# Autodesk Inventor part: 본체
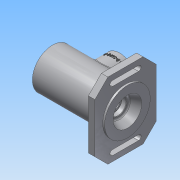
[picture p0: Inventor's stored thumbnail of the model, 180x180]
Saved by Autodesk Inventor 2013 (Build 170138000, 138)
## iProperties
Created: 2017-10
Part Number: 본체
Material: 알루미늄 6061
Document SubType Name: Modeling
Designer: Administrator
Density: 2.71 g/cm^3
Mass: 738.628 g
Surface Area: 652.989 cm^2
Volume: 272.556 cm^3
Author: Administrator
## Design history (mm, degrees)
sketch "스케치1"
  geometry: L1 (-56, 0)-(59, 0); L2 (-56, 0)-(-56, 21); L3 (-56, 31)-(59, 31); L4 (59, 31)-(59, 22); L5 (-56, 21)-(-47, 21); L6 (-47, 21)-(-47, 24); L7 (-47, 24)-(-44, 24); L8 (-44, 24)-(-44, 20); L9 (-31.75, 17.5)-(-31.75, 18.5); L10 (-31.75, 18.5)-(-30, 18.5); L11 (-30, 18.5)-(-30, 17.5); L12 (-30, 17.5)-(-19, 17.5); L13 (-19, 17.5)-(-19, 26); L14 (-19, 26)-(19, 26); L15 (19, 26)-(19, 17.5); L16 (19, 17.5)-(30, 17.5); L17 (30, 17.5)-(30, 16.5); L18 (30, 16.5)-(35, 16.5); L19 (35, 16.5)-(35, 10); L20 (35, 10)-(37.7, 10); L21 (37.7, 10)-(37.7, 12.5); L22 (37.7, 12.5)-(45, 12.5); L23 (45, 12.5)-(45, 16); L24 (45, 16)-(59, 22); L25 (-44, 20)-(-35, 20); L26 (-35, 20)-(-35, 17.5); L27 (-35, 17.5)-(-31.75, 17.5); L28 (59, 22)-(59, 0); L29 (-56, 21)-(-56, 31); 1 further point
  constraints: 58 end point, 17 parallel, 12 perpendicular, 2 collinear, 1 horizontal, 1 point on line
  dimensions: "d0" = 56 distance of L1.start point (0, 0); "d1" = 115 distance of L1.start L1.end; "d2" = 62 diameter of L3 L1; "d3" = 44 diameter of L4.end L1; "d4" = 32 diameter of L23.end L1; "d5" = 25 diameter of L22 L1; "d6" = 20 diameter of L20 L1; "d7" = 33 diameter of L18 L1; "d8" = 48 diameter of L7 L1; "d9" = 37 diameter of L10 L1; "d11" = 52 diameter of L14 L1; "d12" = 11 distance of L15.end L16.end; "d13" = 14 distance between parallel lines of L4 L23; "d14" = 7.3 distance of L21.end L22.end; "d15" = 2.7 distance between parallel lines of L19 L21; "d16" = 5 distance of L17.end L18.end; "d17" = 11 distance of L11.end L12.end; "d18" = 1.75 distance of L9.end L10.end; "d19" = 12 distance between parallel lines of L2 L8; "d20" = 40 diameter of L25 L1; "d21" = 21 distance between parallel lines of L2 L26; "d22" = 3 distance between parallel lines of L6 L8; "d23" = 42 diameter of L5 L1; "d24" = 35 diameter of L12 L1; "d25" = 26 distance from line of L2 L11.end
revolve "회전1" sketch "스케치1" stored, may be unused: angle "d26" = 90 deg
sketch "스케치2"
  geometry: C1 r 31 at (0, 0) reference; C2 r 35 at (0, 0)
  constraints: 1 centre point, 1 coincident
  dimensions: "d27" = 70 diameter of C2
extrude "돌출1" join sketch "스케치2" distance "d29" = 3; taper "d30" = 0 deg
sketch "스케치4"
  geometry: L1 (58, -47)-(-58, -47); L2 (-58, -47)-(-58, 47); L3 (-58, 47)-(58, 47); L4 (58, 47)-(58, -47); L5 (58, -47)-(-58, 47); L6 (-58, -47)-(58, 47); C1 r 31 at (0, 0) reference; C2 r 31 at (0, 0) reference
  constraints: 12 end point, 2 midpoint, 2 parallel, 1 horizontal, 1 perpendicular
  dimensions: "d36" = 116 distance between parallel lines of L4 L2; "d38" = 94 distance between parallel lines of L1 L3
extrude "돌출3" join sketch "스케치4" distance "d39" = 10; taper "d40" = 0 deg
sketch "스케치5"
  geometry: L1 (-58, 47)-(-58, -47) reference; L2 (-50, -20)-(-50, 20); L3 (-42, 20)-(-42, -20); C1 r 31 at (0, 0) reference; A1 r 4 centre (-46, 20) between (-42, 20) and (-50, 20); A2 r 4 centre (-46, -20) between (-50, -20) and (-42, -20)
  constraints: 4 end point, 4 point on circle, 4 tangent, 2 centre point, 2 parallel
  dimensions: "d41" = 20 vertical distance of A1.centre C1.centre; "d42" = 40 distance of A2.centre A1.centre; "d43" = 46 horizontal distance of C1.centre A2.centre; "d44" = 4 radius of A1
extrude "돌출4" cut sketch "스케치5" distance "d45" = 10; taper "d46" = 0 deg
chamfer "모따기1" distance "d47" = 20; stored, may be unused: second distance "d48" = 2, angle "d49" = 45 deg
node "작업 평면1"
sketch "스케치6"
  geometry: C1 r 25 at (0, 0); 1 further point
  constraints: 1 centre point, 1 coincident
  dimensions: "d51" = 50 diameter of C1
extrude "돌출5" join sketch "스케치6" stored distance "d53" = 10; taper "d54" = 0 deg
hole "구멍1" diameter "d57" = 32; stored, may be unused: countersink angle "d61" = 90 deg, drill point angle "d63" = 118 deg; dims "d55" = 10, "d56" = 10, "d58" = 6, "d59" = 4, "d60" = 2, "d62" = 8
fillet "모깎기1" dims "d64" = 3
fillet "모깎기2" dims "d65" = 0.3
chamfer "모따기2" distance "d66" = 0.7; stored, may be unused: second distance "d67" = 2, angle "d68" = 30 deg
node "작업 평면2"
sketch "스케치8"
  geometry: L1 (-25, 0)-(25, 0) reference; L2 (-56, -78)-(-56, -16) reference; 2 further points
  constraints: 1 other
  dimensions: "d70" = 10 vertical distance of point (0, -10) L1.end; "d71" = 56 distance from line of L2 point (0, -10)
feature "엠보싱1" sketch "스케치8" dims "d12" = 11, "d72" = 0.5, "d73" = 0
feature "스레드1" dims "d74" = 10, "d75" = 0
sketch "스케치9"
  geometry: C1 r 16 at (0, 0) reference; 1 further point
  constraints: 1 vertical alignment
  dimensions: "d76" = 20.5 distance of C1.centre point (0, 20.5)
hole "구멍2" sketch "스케치9" at (0, 20.5) diameter "d77" = 2.459; stored, may be unused: countersink angle "d81" = 90 deg, drill point angle "d83" = 118 deg; dims "d78" = 6, "d79" = 4, "d80" = 2, "d82" = 8
chamfer "모따기3" distance "d84" = 1; stored, may be unused: second distance "d85" = 2, angle "d86" = 30 deg
chamfer "모따기4" distance "d87" = 1; stored, may be unused: second distance "d88" = 2, angle "d89" = 30 deg
node "솔리드1"
mirror "대칭1"
mirror "대칭2"
other parameters: "d50" = 47
